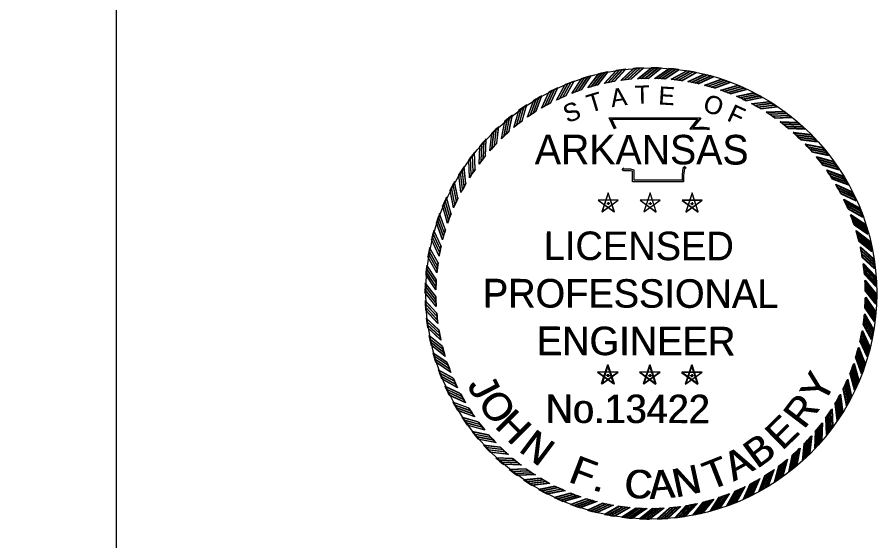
# Model space of a CAD drawing. Extents: x 0 to 19, y -0.6 to 11.3.
# Drawn here: x 16.736 to 19.023, y 7.658 to 9.05 of the extents above; entities that cross this region are included whole.
import ezdxf

# ---------------------------------------------------------------- set-up
doc = ezdxf.new("R2010")
doc.units = 0
for name, color, linetype in [('Default', 7, 'Continuous'), ('G-ANNO-STMP', 7, 'Continuous'), ('G-Border-Paper', 7, 'Continuous'), ('G-No Plot-Stamp-2', 7, 'Continuous')]:
    doc.layers.add(name, color=color, linetype=linetype)

# ---------------------------------------------------------------- blocks, each defined once
blk = doc.blocks.new('STAR')
at = {"layer": 'Default'}
for p, q in [((-0.0001, 0.0615), (-0.0366, -0.0504)), ((0.0362, -0.0503), (0, 0.0617)), ((0.0587, 0.0188), (-0.059, 0.0189)), ((-0.0589, 0.0188), (0.0363, -0.0505)), ((-0.0365, -0.0503), (0.0589, 0.0188)), ((-0.0085, 0), (0.009, 0)), ((0, 0.0063), (0, -0.0085))]:
    blk.add_line(p, q, dxfattribs=at)
blk = doc.blocks.new('RP')
at = {"layer": 'Default'}
for p, q in [((-0.0781, 1.2656), (0.003, 1.33)), ((-0.058, 1.2667), (0.0216, 1.3299)), ((-0.0375, 1.2674), (0.0405, 1.3294)), ((-0.0176, 1.2679), (0.059, 1.3287))]:
    blk.add_line(p, q, dxfattribs=at)
for radius, start, end in [(1.33, 87.4562, 89.8699), (1.268, 90.7933, 93.5307)]:
    blk.add_arc((0, 0), radius, start, end, dxfattribs=at)

msp = doc.modelspace()

# ---------------------------------------------------------------- linework, layer by layer
at = {"layer": 'G-ANNO-STMP'}
for points in [[(18.3256, 8.7521), (18.3116, 8.7824), (18.5542, 8.7826), (18.5339, 8.7571), (18.5504, 8.7573), (18.5641, 8.7575), (18.5779, 8.756)], [(18.3261, 8.7522), (18.3121, 8.7827), (18.5547, 8.782), (18.5344, 8.7566), (18.5509, 8.7567), (18.5646, 8.7569), (18.5784, 8.7553)], [(18.3291, 8.7537), (18.3176, 8.7786), (18.5462, 8.7787), (18.5258, 8.7532), (18.5504, 8.7535), (18.564, 8.7537), (18.5775, 8.7522)], [(18.3295, 8.7538), (18.3181, 8.7788), (18.5468, 8.7781), (18.5263, 8.7526), (18.5509, 8.7529), (18.5644, 8.753), (18.5779, 8.7515)], [(18.5159, 8.6504), (18.5118, 8.647), (18.5104, 8.642), (18.509, 8.6294), (18.509, 8.6127), (18.3736, 8.6127), (18.3736, 8.6353), (18.3736, 8.6403), (18.3681, 8.642), (18.3489, 8.642), (18.3454, 8.6472)], [(18.5161, 8.6499), (18.5119, 8.6466), (18.5105, 8.6415), (18.5091, 8.629), (18.509, 8.6122), (18.3736, 8.6127), (18.3737, 8.6353), (18.3737, 8.6403), (18.3682, 8.642), (18.349, 8.6421), (18.3456, 8.6473)], [(18.5135, 8.6534), (18.5084, 8.6492), (18.5066, 8.6427), (18.5052, 8.6296), (18.5052, 8.6165), (18.3775, 8.6165), (18.3775, 8.6353), (18.3775, 8.6432), (18.3687, 8.6459), (18.3509, 8.6459), (18.3487, 8.6493)], [(18.5136, 8.6529), (18.5085, 8.6488), (18.5067, 8.6423), (18.5053, 8.6292), (18.5052, 8.6161), (18.3775, 8.6165), (18.3775, 8.6353), (18.3776, 8.6432), (18.3688, 8.6459), (18.3511, 8.6459), (18.3488, 8.6494)]]:
    msp.add_lwpolyline(points, dxfattribs=at)
at = {"layer": 'G-Border-Paper'}
msp.add_lwpolyline([(17, 11), (0, 11), (0, 0), (17, 0)], close=True, dxfattribs=at)
at = {"layer": 'G-No Plot-Stamp-2'}
msp.add_circle((18.4233, 8.3154), 0.6, dxfattribs=at)

# ---------------------------------------------------------------- block references
at = {"layer": 'G-ANNO-STMP'}
for name, p, xscale, yscale, rotation in [('RP', (18.4219, 8.3156), 0.45103579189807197, 0.4510357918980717, 13.500000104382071), ('RP', (18.4209, 8.3154), 0.451035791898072, 0.45103579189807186, 13.304199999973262), ('RP', (18.4219, 8.3156), 0.45103579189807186, 0.45103579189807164, 9.000000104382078), ('RP', (18.4209, 8.3154), 0.4510357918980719, 0.4510357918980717, 8.804199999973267), ('RP', (18.4219, 8.3156), 0.45103579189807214, 0.4510357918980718, 4.500000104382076), ('RP', (18.4209, 8.3154), 0.451035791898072, 0.45103579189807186, 4.304199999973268), ('RP', (18.4219, 8.3156), 0.451035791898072, 0.45103579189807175, 1.0438208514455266e-07), ('RP', (18.4209, 8.3154), 0.451035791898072, 0.45103579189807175, -0.19580000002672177), ('RP', (18.4219, 8.3156), 0.451035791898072, 0.45103579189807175, -4.499999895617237), ('RP', (18.4209, 8.3154), 0.4510357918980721, 0.45103579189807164, -4.695800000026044), ('RP', (18.4219, 8.3156), 0.4510357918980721, 0.45103579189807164, -8.999999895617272), ('RP', (18.4209, 8.3154), 0.45103579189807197, 0.45103579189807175, -9.195800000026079), ('RP', (18.4219, 8.3156), 0.4510357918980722, 0.45103579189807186, -13.499999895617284), ('RP', (18.4209, 8.3154), 0.4510357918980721, 0.4510357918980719, -13.695800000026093), ('RP', (18.4219, 8.3156), 0.45103579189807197, 0.45103579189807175, 22.500000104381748), ('RP', (18.4209, 8.3154), 0.451035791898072, 0.4510357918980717, 22.304199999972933), ('RP', (18.4219, 8.3156), 0.45103579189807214, 0.4510357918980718, 18.000000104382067), ('RP', (18.4209, 8.3154), 0.45103579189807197, 0.4510357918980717, 17.804199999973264), ('RP', (18.4219, 8.3156), 0.45103579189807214, 0.4510357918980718, -17.99999989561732), ('RP', (18.4209, 8.3154), 0.4510357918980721, 0.4510357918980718, -18.19580000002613), ('RP', (18.4219, 8.3156), 0.4510357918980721, 0.4510357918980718, -22.499999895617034), ('RP', (18.4209, 8.3154), 0.45103579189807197, 0.4510357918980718, -22.695800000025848), ('RP', (18.4219, 8.3156), 0.451035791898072, 0.45103579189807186, 27.000000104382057), ('RP', (18.4209, 8.3154), 0.45103579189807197, 0.4510357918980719, 26.804199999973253), ('RP', (18.4219, 8.3156), 0.45103579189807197, 0.4510357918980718, -26.999999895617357), ('RP', (18.4209, 8.3154), 0.45103579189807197, 0.45103579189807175, -27.19580000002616), ('RP', (18.4219, 8.3156), 0.45103579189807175, 0.45103579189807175, 31.50000010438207), ('RP', (18.4209, 8.3154), 0.4510357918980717, 0.4510357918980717, 31.30419999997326), ('RP', (18.4219, 8.3156), 0.45103579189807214, 0.45103579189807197, -31.499999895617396), ('RP', (18.4209, 8.3154), 0.4510357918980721, 0.45103579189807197, -31.695800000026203), ('RP', (18.4219, 8.3156), 0.4510357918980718, 0.45103579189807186, 36.00000010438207), ('RP', (18.4209, 8.3154), 0.4510357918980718, 0.45103579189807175, 35.80419999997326), ('RP', (18.4219, 8.3156), 0.4510357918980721, 0.451035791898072, -35.999999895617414), ('RP', (18.4209, 8.3154), 0.451035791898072, 0.45103579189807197, -36.195800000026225), ('RP', (18.4219, 8.3156), 0.4510357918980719, 0.45103579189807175, 40.50000010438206), ('RP', (18.4209, 8.3154), 0.45103579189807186, 0.45103579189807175, 40.30419999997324), ('RP', (18.4219, 8.3156), 0.45103579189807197, 0.451035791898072, -40.49999989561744), ('RP', (18.4209, 8.3154), 0.45103579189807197, 0.45103579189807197, -40.69580000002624), ('RP', (18.4219, 8.3156), 0.45103579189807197, 0.45103579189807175, -44.99999989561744), ('RP', (18.4209, 8.3154), 0.4510357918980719, 0.45103579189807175, -45.19580000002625), ('RP', (18.4219, 8.3156), 0.45103579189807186, 0.451035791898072, 45.00000010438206), ('RP', (18.4209, 8.3154), 0.45103579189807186, 0.45103579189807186, 44.80419999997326), ('RP', (18.4219, 8.3156), 0.45103579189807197, 0.451035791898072, 49.500000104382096), ('RP', (18.4209, 8.3154), 0.451035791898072, 0.451035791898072, 49.304199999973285), ('RP', (18.4219, 8.3156), 0.4510357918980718, 0.4510357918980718, -49.499999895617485), ('RP', (18.4209, 8.3154), 0.4510357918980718, 0.45103579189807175, -49.695800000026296), ('RP', (18.4219, 8.3156), 0.45103579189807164, 0.45103579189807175, -53.999999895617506), ('RP', (18.4209, 8.3154), 0.45103579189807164, 0.4510357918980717, -54.1958000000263), ('RP', (18.4219, 8.3156), 0.45103579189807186, 0.4510357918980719, 54.00000010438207), ('RP', (18.4209, 8.3154), 0.4510357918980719, 0.4510357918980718, 53.804199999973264), ('RP', (18.4209, 8.3154), 0.45103579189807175, 0.4510357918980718, 58.304199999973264), ('RP', (18.4219, 8.3156), 0.4510357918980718, 0.4510357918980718, 58.50000010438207), ('RP', (18.4219, 8.3156), 0.4510357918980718, 0.4510357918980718, -58.49999989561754), ('RP', (18.4209, 8.3154), 0.45103579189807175, 0.45103579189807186, -58.69580000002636), ('RP', (18.4209, 8.3154), 0.45103579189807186, 0.4510357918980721, 62.804199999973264), ('RP', (18.4219, 8.3156), 0.4510357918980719, 0.451035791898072, 63.00000010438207), ('RP', (18.4219, 8.3156), 0.4510357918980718, 0.45103579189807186, -62.99999989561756), ('RP', (18.4209, 8.3154), 0.4510357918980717, 0.4510357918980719, -63.19580000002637), ('STAR', (18.3085, 8.5553), 0.451035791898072, 0.45103579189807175, -0.19580000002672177), ('STAR', (18.3087, 8.5551), 0.451035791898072, 0.45103579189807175, 1.0438208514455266e-07), ('STAR', (18.4201, 8.5549), 0.451035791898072, 0.45103579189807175, -0.19580000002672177), ('STAR', (18.4203, 8.5551), 0.451035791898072, 0.45103579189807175, 1.0438208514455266e-07), ('STAR', (18.5316, 8.5545), 0.451035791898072, 0.45103579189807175, -0.19580000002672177), ('STAR', (18.5318, 8.5551), 0.451035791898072, 0.45103579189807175, 1.0438208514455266e-07), ('RP', (18.4219, 8.3156), 0.45103579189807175, 0.45103579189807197, -67.49999989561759), ('RP', (18.4209, 8.3154), 0.45103579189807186, 0.4510357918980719, 67.30419999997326), ('RP', (18.4219, 8.3156), 0.4510357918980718, 0.45103579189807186, 67.50000010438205), ('RP', (18.4209, 8.3154), 0.4510357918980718, 0.45103579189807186, -67.69580000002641), ('RP', (18.4209, 8.3154), 0.4510357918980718, 0.4510357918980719, -72.19580000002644), ('RP', (18.4219, 8.3156), 0.4510357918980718, 0.45103579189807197, -71.99999989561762), ('RP', (18.4209, 8.3154), 0.45103579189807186, 0.451035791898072, 71.80419999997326), ('RP', (18.4219, 8.3156), 0.4510357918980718, 0.45103579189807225, 72.00000010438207), ('RP', (18.4209, 8.3154), 0.4510357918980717, 0.4510357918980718, -76.69580000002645), ('RP', (18.4219, 8.3156), 0.4510357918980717, 0.4510357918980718, -76.49999989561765), ('RP', (18.4209, 8.3154), 0.4510357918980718, 0.4510357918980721, 76.30419999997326), ('RP', (18.4219, 8.3156), 0.4510357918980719, 0.451035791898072, 76.50000010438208), ('RP', (18.4209, 8.3154), 0.4510357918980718, 0.45103579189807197, -81.19580000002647), ('RP', (18.4219, 8.3156), 0.45103579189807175, 0.45103579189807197, -80.99999989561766), ('RP', (18.4209, 8.3154), 0.4510357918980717, 0.45103579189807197, 80.80419999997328), ('RP', (18.4219, 8.3156), 0.4510357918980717, 0.451035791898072, 81.0000001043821), ('RP', (18.4209, 8.3154), 0.4510357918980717, 0.4510357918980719, -85.69580000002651), ('RP', (18.4219, 8.3156), 0.45103579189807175, 0.4510357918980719, -85.49999989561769), ('RP', (18.4209, 8.3154), 0.4510357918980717, 0.4510357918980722, 85.30419999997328), ('RP', (18.4219, 8.3156), 0.4510357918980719, 0.4510357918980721, 85.5000001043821), ('RP', (18.4209, 8.3154), 0.45103579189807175, 0.451035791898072, -90.19580000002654), ('RP', (18.4219, 8.3156), 0.4510357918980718, 0.45103579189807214, -89.99999989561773), ('RP', (18.4209, 8.3154), 0.45103579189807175, 0.451035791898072, 89.80419999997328), ('RP', (18.4219, 8.3156), 0.45103579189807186, 0.45103579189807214, 90.0000001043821), ('RP', (18.4209, 8.3154), 0.45103579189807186, 0.451035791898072, -94.69580000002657), ('RP', (18.4219, 8.3156), 0.45103579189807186, 0.451035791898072, -94.49999989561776), ('RP', (18.4209, 8.3154), 0.45103579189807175, 0.4510357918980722, 94.30419999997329), ('RP', (18.4219, 8.3156), 0.45103579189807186, 0.4510357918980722, 94.5000001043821), ('RP', (18.4209, 8.3154), 0.45103579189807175, 0.45103579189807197, -99.19580000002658), ('RP', (18.4219, 8.3156), 0.4510357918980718, 0.4510357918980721, -98.99999989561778), ('RP', (18.4209, 8.3154), 0.4510357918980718, 0.45103579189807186, 98.8041999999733), ('RP', (18.4219, 8.3156), 0.45103579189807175, 0.4510357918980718, 99.0000001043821), ('RP', (18.4209, 8.3154), 0.4510357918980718, 0.4510357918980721, -103.69580000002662), ('RP', (18.4219, 8.3156), 0.45103579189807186, 0.45103579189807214, -103.49999989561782), ('RP', (18.4209, 8.3154), 0.4510357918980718, 0.4510357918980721, 103.30419999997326), ('RP', (18.4219, 8.3156), 0.45103579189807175, 0.451035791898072, 103.50000010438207), ('RP', (18.4209, 8.3154), 0.45103579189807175, 0.4510357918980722, 107.80419999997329), ('RP', (18.4209, 8.3154), 0.45103579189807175, 0.45103579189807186, -108.19580000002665), ('RP', (18.4219, 8.3156), 0.4510357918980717, 0.451035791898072, -107.99999989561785), ('RP', (18.4219, 8.3156), 0.45103579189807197, 0.45103579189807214, 108.0000001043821), ('RP', (18.4209, 8.3154), 0.45103579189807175, 0.45103579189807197, 112.30419999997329), ('RP', (18.4219, 8.3156), 0.4510357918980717, 0.45103579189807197, 112.5000001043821), ('STAR', (18.3069, 8.0978), 0.451035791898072, 0.45103579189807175, -0.19580000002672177), ('STAR', (18.3087, 8.0976), 0.451035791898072, 0.45103579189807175, 1.0438208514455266e-07), ('STAR', (18.4185, 8.0974), 0.451035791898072, 0.45103579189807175, -0.19580000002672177), ('STAR', (18.4203, 8.0976), 0.451035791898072, 0.45103579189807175, 1.0438208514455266e-07), ('STAR', (18.5301, 8.097), 0.451035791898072, 0.45103579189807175, -0.19580000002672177), ('STAR', (18.5318, 8.0976), 0.451035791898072, 0.45103579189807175, 1.0438208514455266e-07), ('RP', (18.4209, 8.3154), 0.4510357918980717, 0.4510357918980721, -112.69580000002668), ('RP', (18.4219, 8.3156), 0.45103579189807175, 0.4510357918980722, -112.49999989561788), ('RP', (18.4209, 8.3154), 0.4510357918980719, 0.45103579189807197, 116.80419999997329), ('RP', (18.4219, 8.3156), 0.4510357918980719, 0.45103579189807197, 117.0000001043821), ('RP', (18.4209, 8.3154), 0.4510357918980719, 0.4510357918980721, -117.19580000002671), ('RP', (18.4219, 8.3156), 0.451035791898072, 0.4510357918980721, -116.9999998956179), ('RP', (18.4209, 8.3154), 0.45103579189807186, 0.45103579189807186, 121.30419999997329), ('RP', (18.4219, 8.3156), 0.45103579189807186, 0.45103579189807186, 121.5000001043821), ('RP', (18.4209, 8.3154), 0.4510357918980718, 0.4510357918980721, -121.69580000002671), ('RP', (18.4219, 8.3156), 0.4510357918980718, 0.4510357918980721, -121.4999998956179), ('RP', (18.4209, 8.3154), 0.4510357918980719, 0.45103579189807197, -126.19580000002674), ('RP', (18.4219, 8.3156), 0.45103579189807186, 0.45103579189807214, -125.99999989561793), ('RP', (18.4209, 8.3154), 0.45103579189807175, 0.45103579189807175, 125.80419999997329), ('RP', (18.4219, 8.3156), 0.4510357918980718, 0.4510357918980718, 126.00000010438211), ('RP', (18.4209, 8.3154), 0.4510357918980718, 0.4510357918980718, 130.3041999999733), ('RP', (18.4219, 8.3156), 0.4510357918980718, 0.45103579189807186, 130.50000010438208), ('RP', (18.4209, 8.3154), 0.45103579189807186, 0.45103579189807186, -130.6958000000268), ('RP', (18.4219, 8.3156), 0.45103579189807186, 0.4510357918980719, -130.49999989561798), ('RP', (18.4209, 8.3154), 0.45103579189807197, 0.45103579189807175, 134.80419999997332), ('RP', (18.4219, 8.3156), 0.45103579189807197, 0.4510357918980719, 135.00000010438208), ('RP', (18.4209, 8.3154), 0.45103579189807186, 0.45103579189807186, -135.19580000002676), ('RP', (18.4219, 8.3156), 0.45103579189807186, 0.451035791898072, -134.99999989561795), ('RP', (18.4209, 8.3154), 0.45103579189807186, 0.45103579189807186, 139.30419999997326), ('RP', (18.4219, 8.3156), 0.4510357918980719, 0.45103579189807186, 139.50000010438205), ('RP', (18.4209, 8.3154), 0.4510357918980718, 0.45103579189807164, -139.69580000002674), ('RP', (18.4219, 8.3156), 0.4510357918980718, 0.45103579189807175, -139.49999989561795), ('RP', (18.4209, 8.3154), 0.451035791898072, 0.45103579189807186, 143.8041999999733), ('RP', (18.4219, 8.3156), 0.4510357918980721, 0.4510357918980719, 144.00000010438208), ('RP', (18.4209, 8.3154), 0.4510357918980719, 0.4510357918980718, -144.19580000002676), ('RP', (18.4219, 8.3156), 0.45103579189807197, 0.45103579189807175, -143.99999989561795), ('RP', (18.4209, 8.3154), 0.45103579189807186, 0.45103579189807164, -148.69580000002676), ('RP', (18.4219, 8.3156), 0.45103579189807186, 0.45103579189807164, -148.49999989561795), ('RP', (18.4209, 8.3154), 0.4510357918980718, 0.45103579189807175, 148.3041999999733), ('RP', (18.4219, 8.3156), 0.4510357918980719, 0.4510357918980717, 148.50000010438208), ('RP', (18.4219, 8.3156), 0.4510357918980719, 0.4510357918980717, -152.99999989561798), ('RP', (18.4209, 8.3154), 0.4510357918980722, 0.4510357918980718, 152.8041999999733), ('RP', (18.4219, 8.3156), 0.4510357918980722, 0.45103579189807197, 153.00000010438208), ('RP', (18.4209, 8.3154), 0.451035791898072, 0.4510357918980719, -157.6958000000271), ('RP', (18.4219, 8.3156), 0.45103579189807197, 0.45103579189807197, -157.4999998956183), ('RP', (18.4209, 8.3154), 0.45103579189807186, 0.45103579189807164, -153.1958000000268), ('RP', (18.4209, 8.3154), 0.45103579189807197, 0.4510357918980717, 157.3041999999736), ('RP', (18.4219, 8.3156), 0.4510357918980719, 0.4510357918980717, 157.50000010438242), ('RP', (18.4209, 8.3154), 0.4510357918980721, 0.4510357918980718, 161.8041999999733), ('RP', (18.4219, 8.3156), 0.4510357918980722, 0.4510357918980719, 162.00000010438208), ('RP', (18.4209, 8.3154), 0.45103579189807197, 0.4510357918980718, -162.19580000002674), ('RP', (18.4219, 8.3156), 0.45103579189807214, 0.45103579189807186, -161.99999989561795), ('RP', (18.4209, 8.3154), 0.4510357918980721, 0.4510357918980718, 166.3041999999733), ('RP', (18.4219, 8.3156), 0.4510357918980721, 0.4510357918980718, 166.50000010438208), ('RP', (18.4209, 8.3154), 0.45103579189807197, 0.4510357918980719, 170.8041999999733), ('RP', (18.4219, 8.3156), 0.45103579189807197, 0.4510357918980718, 171.00000010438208), ('RP', (18.4209, 8.3154), 0.4510357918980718, 0.4510357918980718, -171.19580000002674), ('RP', (18.4219, 8.3156), 0.45103579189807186, 0.45103579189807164, -170.99999989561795), ('RP', (18.4209, 8.3154), 0.451035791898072, 0.45103579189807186, -166.69580000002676), ('RP', (18.4219, 8.3156), 0.45103579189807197, 0.4510357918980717, -166.49999989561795), ('RP', (18.4209, 8.3154), 0.451035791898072, 0.45103579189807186, 175.3041999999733), ('RP', (18.4219, 8.3156), 0.4510357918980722, 0.4510357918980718, 175.50000010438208), ('RP', (18.4209, 8.3154), 0.451035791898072, 0.45103579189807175, 179.8041999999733), ('RP', (18.4219, 8.3156), 0.45103579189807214, 0.45103579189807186, -179.99999989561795), ('RP', (18.4209, 8.3154), 0.45103579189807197, 0.4510357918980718, -175.69580000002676), ('RP', (18.4219, 8.3156), 0.45103579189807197, 0.45103579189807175, -175.49999989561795)]:
    msp.add_blockref(name, p, dxfattribs=dict(at, xscale=xscale, yscale=yscale, rotation=rotation))

# ---------------------------------------------------------------- texts
for s, height, rotation, p in [('T', 0.0479, 16.9015, (18.2601, 8.7953)), ('T', 0.0479, 16.7057, (18.2607, 8.7957)), ('A', 0.0479, 8.6788, (18.3182, 8.8105)), ('A', 0.0479, 8.483, (18.3189, 8.8107)), ('T', 0.0479, 1.4789, (18.38, 8.82)), ('T', 0.0479, 1.2831, (18.3807, 8.82)), ('E', 0.0479, 356.672, (18.4412, 8.8185)), ('E', 0.0479, 356.4762, (18.4419, 8.8183)), ('O', 0.0479, 341.2218, (18.5574, 8.8021)), ('O', 0.0479, 341.026, (18.5581, 8.8015)), ('S', 0.0479, 19.7726, (18.1992, 8.768)), ('S', 0.0479, 19.5768, (18.1998, 8.7686)), ('F', 0.0479, 335.3628, (18.6219, 8.7769)), ('F', 0.0479, 335.167, (18.6225, 8.7761)), ('ARKANSAS', 0.0781, 0, (18.1132, 8.6591)), ('ARKANSAS', 0.0781, 359.8042, (18.1134, 8.66)), ('LICENSED', 0.07561, 359.8042, (18.1368, 8.405)), ('LICENSED', 0.07561, 0, (18.1375, 8.4042)), ('PROFESSIONAL', 0.075612, 359.8042, (17.9743, 8.2791)), ('PROFESSIONAL', 0.075612, 0, (17.9755, 8.2777)), ('ENGINEER', 0.07561, 359.8042, (18.1179, 8.1522)), ('ENGINEER', 0.07561, 0, (18.1195, 8.1513)), ('Y', 0.0756, 62.5392, (18.8819, 8.0186)), ('Y', 0.0756, 62.735, (18.8839, 8.0204)), ('J', 0.0756, 297.2813, (17.9322, 8.0724)), ('J', 0.0756, 297.4771, (17.934, 8.0709)), ('O', 0.0756, 304.1899, (17.959, 8.026)), ('O', 0.0756, 304.3857, (17.961, 8.0246)), ('No.13422', 0.07531, 359.8042, (18.1412, 7.9718)), ('No.13422', 0.07531, 0, (18.1434, 7.9711)), ('R', 0.0756, 52.7437, (18.8291, 7.9521)), ('R', 0.0756, 52.9395, (18.8313, 7.9536)), ('H', 0.0756, 314.7447, (18.0036, 7.9609)), ('H', 0.0756, 314.9405, (18.0058, 7.9596)), ('E', 0.0756, 44.306, (18.7715, 7.8958)), ('E', 0.0756, 44.5018, (18.7739, 7.8971)), ('N', 0.0756, 322.9417, (18.0674, 7.8976)), ('N', 0.0756, 323.1375, (18.0698, 7.8966)), ('B', 0.0756, 36.505, (18.7047, 7.8477)), ('B', 0.0756, 36.7008, (18.7074, 7.8488)), ('A', 0.0756, 28.8562, (18.6419, 7.8147)), ('A', 0.0756, 29.052, (18.6447, 7.8156)), ('F', 0.0756, 339.0288, (18.1994, 7.8157)), ('F', 0.0756, 339.2246, (18.2021, 7.8152)), ('T', 0.0756, 21.4329, (18.5791, 7.791)), ('T', 0.0756, 21.6287, (18.5819, 7.7917)), ('C', 0.0756, 356.1028, (18.3494, 7.7733)), ('C', 0.0756, 356.2986, (18.3523, 7.7732)), ('A', 0.0756, 3.9092, (18.4187, 7.7683)), ('A', 0.0756, 4.105, (18.4216, 7.7685)), ('N', 0.0756, 12.0703, (18.4879, 7.7722)), ('N', 0.0756, 12.2661, (18.4907, 7.7726)), ('.', 0.0756, 344.7037, (18.2639, 7.7934)), ('.', 0.0756, 344.8995, (18.2667, 7.793))]:
    msp.add_text(s, height=height, rotation=rotation, dxfattribs=at).set_placement(p)

doc.saveas('drawing.dxf')
